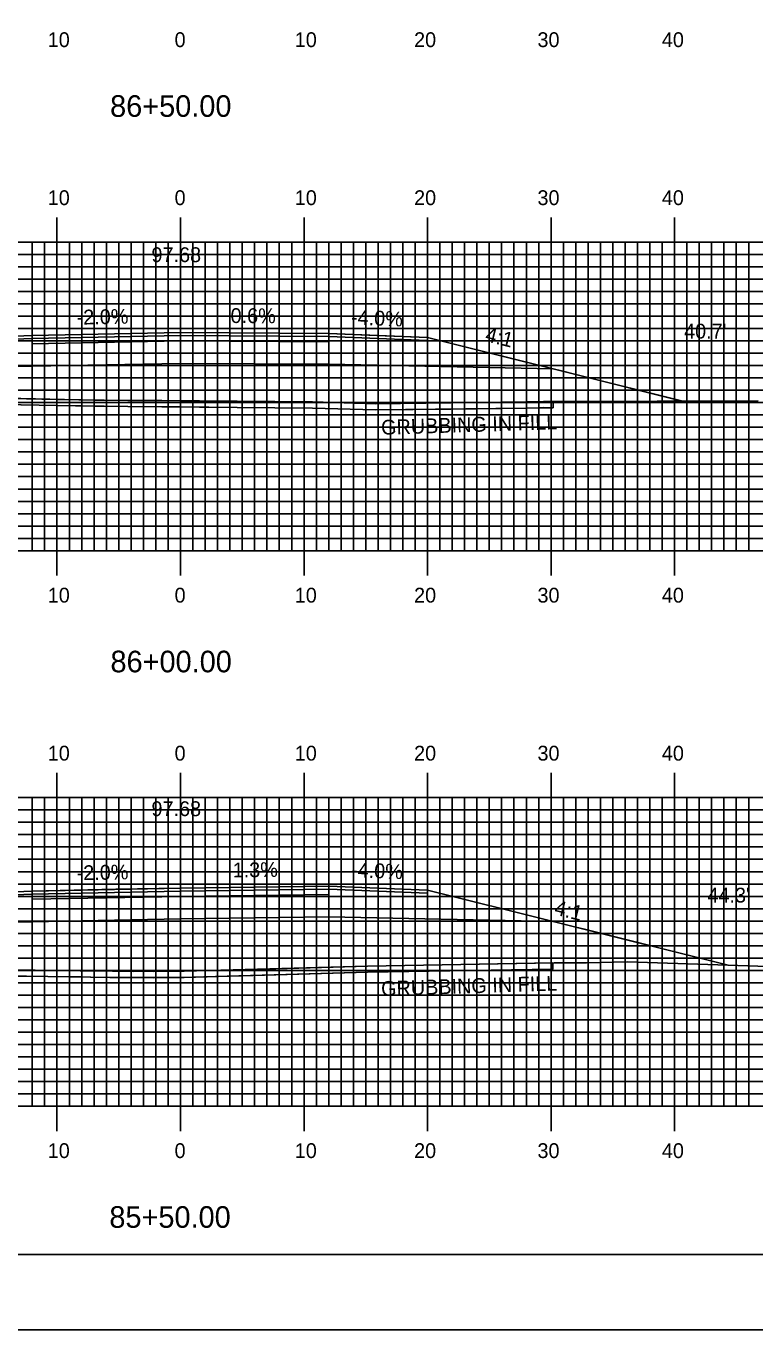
# Model space of a CAD drawing. Extents: x 1763759 to 1764102, y 442591 to 442811.
# Drawn here: x 1763911.8 to 1763970.8, y 442590.5 to 442696.2 of the extents above; entities that cross this region are included whole.
import ezdxf

# ---------------------------------------------------------------- set-up
doc = ezdxf.new("R2010")
doc.units = 0
for name, color, linetype in [('ANNOTATION', 7, 'Continuous'), ('BORDER', 7, 'Continuous'), ('D_Roadway_Centerline', 7, 'Continuous'), ('D_Roadway_Centerline_Text', 7, 'Continuous'), ('D_Roadway_Edge_Shoulder', 7, 'Continuous'), ('D_Roadway_Edge_TW', 7, 'Continuous'), ('D_Roadway_Pavement', 7, 'Continuous'), ('D_Roadway_SlopeLines', 7, 'Continuous'), ('D_Roadway_SubGrade', 7, 'Continuous'), ('D_Text_Standard', 7, 'Continuous'), ('GRUBBING IN FILL', 7, 'Continuous'), ('H_V ANNOTATION', 7, 'Continuous'), ('MAJOR', 7, 'Continuous'), ('MINOR', 7, 'Continuous'), ('PLOT BOUNDARY', 7, 'Continuous'), ('S_Roadway_Centerline', 7, 'Continuous')]:
    doc.layers.add(name, color=color, linetype=linetype)

msp = doc.modelspace()

# ---------------------------------------------------------------- linework, layer by layer
at = {"layer": 'BORDER'}
msp.add_lwpolyline([(1763774.72, 442596.67), (1764094.72, 442596.67), (1764094.72, 442806.67), (1763774.72, 442806.67)], close=True, dxfattribs=at)
at = {"layer": 'D_Roadway_Centerline'}
for points in [[(1763887.29, 442666.53), (1763894.14, 442668.24), (1763894.15, 442668.24), (1763901.63, 442670.11), (1763904.32, 442670.79), (1763906.87, 442670.89), (1763912.31, 442671.11), (1763912.32, 442671.11), (1763924.31, 442671.35), (1763924.32, 442671.35), (1763924.32, 442671.35), (1763936.32, 442671.27), (1763936.32, 442671.27), (1763940.22, 442671.11), (1763944.32, 442670.95), (1763944.33, 442670.95), (1763950.59, 442669.38), (1763954.49, 442668.4), (1763955.16, 442668.24), (1763956.32, 442667.95), (1763964.82, 442665.82), (1763964.98, 442665.78)], [(1763883.9, 442620.67), (1763894.14, 442623.23), (1763894.14, 442623.24), (1763904.32, 442625.78), (1763904.32, 442625.78), (1763912.31, 442626.1), (1763912.32, 442626.1), (1763919.08, 442626.24), (1763924.31, 442626.34), (1763924.32, 442626.34), (1763936.31, 442626.5), (1763936.32, 442626.5), (1763936.32, 442626.5), (1763944.32, 442626.18), (1763954.49, 442623.64), (1763954.49, 442623.63), (1763956.32, 442623.18), (1763957.04, 442623), (1763968.66, 442620.09)]]:
    msp.add_lwpolyline(points, dxfattribs=at)
at = {"layer": 'D_Roadway_Edge_Shoulder'}
for points in [[(1763912.32, 442671.11), (1763904.32, 442670.79), (1763904.32, 442670.54), (1763912.32, 442670.86)], [(1763936.32, 442671.27), (1763944.32, 442670.95), (1763944.32, 442670.7), (1763936.32, 442671.02)], [(1763912.32, 442626.1), (1763904.32, 442625.78), (1763904.32, 442625.53), (1763912.32, 442625.85)], [(1763936.32, 442626.5), (1763944.32, 442626.18), (1763944.32, 442625.93), (1763936.32, 442626.25)]]:
    msp.add_lwpolyline(points, close=True, dxfattribs=at)
at = {"layer": 'D_Roadway_Edge_TW'}
for points in [[(1763912.32, 442670.86), (1763912.32, 442671.11), (1763924.32, 442671.35), (1763936.32, 442671.27), (1763936.32, 442671.02), (1763924.32, 442671.1)], [(1763936.32, 442671.27), (1763936.32, 442671.27), (1763936.32, 442671.02), (1763936.32, 442671.02)], [(1763912.32, 442625.85), (1763912.32, 442626.1), (1763924.32, 442626.34), (1763936.32, 442626.5), (1763936.32, 442626.25), (1763924.32, 442626.09)], [(1763936.32, 442626.5), (1763936.32, 442626.5), (1763936.32, 442626.25), (1763936.32, 442626.25)]]:
    msp.add_lwpolyline(points, close=True, dxfattribs=at)
at = {"layer": 'D_Roadway_Pavement'}
for points in [[(1763912.32, 442670.44), (1763912.32, 442670.86), (1763924.32, 442671.1), (1763936.32, 442671.02), (1763936.32, 442670.6), (1763924.32, 442670.68)], [(1763936.32, 442671.02), (1763936.32, 442671.02), (1763936.32, 442670.6), (1763936.32, 442670.6)], [(1763912.32, 442625.43), (1763912.32, 442625.85), (1763924.32, 442626.09), (1763936.32, 442626.25), (1763936.32, 442625.83), (1763924.32, 442625.67)], [(1763936.32, 442626.25), (1763936.32, 442626.25), (1763936.32, 442625.83), (1763936.32, 442625.83)]]:
    msp.add_lwpolyline(points, close=True, dxfattribs=at)
for points in [[(1763936.32, 442671.02), (1763936.32, 442670.6)], [(1763936.32, 442671.02), (1763936.32, 442670.6)], [(1763936.32, 442671.02), (1763936.32, 442670.6)], [(1763936.32, 442626.25), (1763936.32, 442625.83)], [(1763936.32, 442626.25), (1763936.32, 442625.83)], [(1763936.32, 442626.25), (1763936.32, 442625.83)]]:
    msp.add_lwpolyline(points, dxfattribs=at)
at = {"layer": 'D_Roadway_SlopeLines'}
for points in [[(1763944.32, 442670.95), (1763954.49, 442668.4), (1763956.32, 442667.95), (1763964.98, 442665.78)], [(1763944.32, 442626.18), (1763954.49, 442623.63), (1763956.32, 442623.18), (1763968.66, 442620.09)]]:
    msp.add_lwpolyline(points, dxfattribs=at)
at = {"layer": 'D_Roadway_SubGrade'}
for points in [[(1763904.32, 442670.54), (1763912.32, 442670.86), (1763912.32, 442670.44), (1763912.32, 442668.61), (1763894.14, 442668.24), (1763904.32, 442670.79)], [(1763912.32, 442668.61), (1763912.32, 442670.44), (1763924.32, 442670.68), (1763936.32, 442670.6), (1763936.32, 442668.77), (1763924.32, 442668.85)], [(1763936.32, 442670.6), (1763936.32, 442671.02), (1763944.32, 442670.7), (1763944.32, 442670.95), (1763954.49, 442668.4), (1763936.32, 442668.77)], [(1763936.32, 442670.6), (1763936.32, 442670.6), (1763936.32, 442668.77), (1763936.32, 442668.77)], [(1763904.32, 442625.53), (1763912.32, 442625.85), (1763912.32, 442625.43), (1763912.32, 442623.6), (1763894.14, 442623.24), (1763904.32, 442625.78)], [(1763912.32, 442623.6), (1763912.32, 442625.43), (1763924.32, 442625.67), (1763936.32, 442625.83), (1763936.32, 442624), (1763924.32, 442623.84)], [(1763936.32, 442625.83), (1763936.32, 442626.25), (1763944.32, 442625.93), (1763944.32, 442626.18), (1763954.49, 442623.63), (1763936.32, 442624)], [(1763936.32, 442625.83), (1763936.32, 442625.83), (1763936.32, 442624), (1763936.32, 442624)]]:
    msp.add_lwpolyline(points, close=True, dxfattribs=at)
at = {"layer": 'GRUBBING IN FILL'}
for p, q in [((1763954.49, 442665.75), (1763954.49, 442665.25)), ((1763954.47, 442619.78), (1763954.47, 442620.28))]:
    msp.add_line(p, q, dxfattribs=at)
for points in [[(1763894.14, 442668.24), (1763912.32, 442668.61), (1763924.32, 442668.85), (1763936.32, 442668.77), (1763954.49, 442668.4)], [(1763894.14, 442665.85), (1763899.76, 442665.71), (1763911.39, 442665.49), (1763917.28, 442665.37), (1763922.81, 442665.34), (1763935.01, 442665.23), (1763940.12, 442665.08), (1763952.29, 442665.22), (1763953.27, 442665.24), (1763953.7, 442665.26), (1763954.47, 442665.25)], [(1763894.22, 442619.74), (1763903.78, 442619.27), (1763908.34, 442619.25), (1763918.82, 442619.1), (1763922.15, 442619.08), (1763924.62, 442619.11), (1763939.47, 442619.52), (1763954.47, 442619.78)]]:
    msp.add_lwpolyline(points, dxfattribs=at)
for points in [[(1763894.14, 442666.35), (1763894.14, 442665.85), (1763896.95, 442665.78), (1763905.58, 442665.6), (1763914.34, 442665.43), (1763920.05, 442665.35), (1763924.32, 442665.32), (1763924.32, 442665.82), (1763920.05, 442665.85), (1763914.34, 442665.93), (1763905.58, 442666.1), (1763899.76, 442666.21)], [(1763894.14, 442666.35), (1763894.14, 442665.85), (1763896.95, 442665.78), (1763905.58, 442665.6), (1763914.34, 442665.43), (1763920.05, 442665.35), (1763924.32, 442665.32), (1763924.32, 442665.82), (1763920.05, 442665.85), (1763914.34, 442665.93), (1763905.58, 442666.1), (1763899.76, 442666.21)], [(1763924.32, 442665.82), (1763928.91, 442665.78), (1763935.01, 442665.73), (1763937.57, 442665.66), (1763940.12, 442665.58), (1763946.2, 442665.65), (1763954.49, 442665.75), (1763954.49, 442665.25), (1763952.29, 442665.22), (1763946.2, 442665.15), (1763940.12, 442665.08), (1763935.01, 442665.23), (1763928.91, 442665.28), (1763924.32, 442665.32)], [(1763924.32, 442665.82), (1763928.91, 442665.78), (1763935.01, 442665.73), (1763937.57, 442665.66), (1763940.12, 442665.58), (1763946.2, 442665.65), (1763954.49, 442665.75), (1763954.49, 442665.25), (1763952.29, 442665.22), (1763946.2, 442665.15), (1763940.12, 442665.08), (1763935.01, 442665.23), (1763928.91, 442665.28), (1763924.32, 442665.32)], [(1763894.22, 442619.74), (1763903.78, 442619.27), (1763913.58, 442619.17), (1763916.38, 442619.14), (1763917.03, 442619.13), (1763918.6, 442619.1), (1763920.48, 442619.09), (1763924.32, 442619.1), (1763924.32, 442619.6), (1763920.48, 442619.59), (1763918.82, 442619.6), (1763913.58, 442619.67), (1763908.34, 442619.75), (1763903.78, 442619.77), (1763897.63, 442620.07), (1763894.22, 442620.24)], [(1763894.22, 442619.74), (1763903.78, 442619.27), (1763913.58, 442619.17), (1763916.38, 442619.14), (1763917.03, 442619.13), (1763918.6, 442619.1), (1763920.48, 442619.09), (1763924.32, 442619.1), (1763924.32, 442619.6), (1763920.48, 442619.59), (1763918.82, 442619.6), (1763913.58, 442619.67), (1763908.34, 442619.75), (1763903.78, 442619.77), (1763897.63, 442620.07), (1763894.22, 442620.24)], [(1763924.32, 442619.6), (1763932.04, 442619.81), (1763939.47, 442620.02), (1763947.01, 442620.15), (1763954.47, 442620.28), (1763954.47, 442619.78), (1763939.47, 442619.52), (1763924.32, 442619.1)], [(1763924.32, 442619.6), (1763932.04, 442619.81), (1763939.47, 442620.02), (1763947.01, 442620.15), (1763954.47, 442620.28), (1763954.47, 442619.78), (1763939.47, 442619.52), (1763924.32, 442619.1)]]:
    msp.add_lwpolyline(points, close=True, dxfattribs=at)
at = {"layer": 'MAJOR'}
for p, q in [((1763914.32, 442680.67), (1763914.32, 442678.67)), ((1763924.32, 442680.67), (1763924.32, 442678.67)), ((1763934.32, 442680.67), (1763934.32, 442678.67)), ((1763944.32, 442680.67), (1763944.32, 442678.67)), ((1763954.32, 442680.67), (1763954.32, 442678.67)), ((1763964.32, 442680.67), (1763964.32, 442678.67)), ((1763784.32, 442678.67), (1764064.32, 442678.67)), ((1763784.32, 442678.67), (1764064.32, 442678.67)), ((1763914.32, 442653.67), (1763914.32, 442678.67)), ((1763924.32, 442653.67), (1763924.32, 442678.67)), ((1763934.32, 442653.67), (1763934.32, 442678.67)), ((1763944.32, 442653.67), (1763944.32, 442678.67)), ((1763954.32, 442653.67), (1763954.32, 442678.67)), ((1763964.32, 442653.67), (1763964.32, 442678.67)), ((1763784.32, 442673.67), (1764064.32, 442673.67)), ((1763784.32, 442668.67), (1764064.32, 442668.67)), ((1763784.32, 442663.67), (1764064.32, 442663.67)), ((1763784.32, 442658.67), (1764064.32, 442658.67)), ((1763784.32, 442653.67), (1764064.32, 442653.67)), ((1763784.32, 442653.67), (1764064.32, 442653.67)), ((1763914.32, 442651.66), (1763914.32, 442653.67)), ((1763924.32, 442651.66), (1763924.32, 442653.67)), ((1763934.32, 442651.66), (1763934.32, 442653.67)), ((1763944.32, 442651.66), (1763944.32, 442653.67)), ((1763954.32, 442651.66), (1763954.32, 442653.67)), ((1763964.32, 442651.66), (1763964.32, 442653.67)), ((1763914.32, 442635.67), (1763914.32, 442633.67)), ((1763924.32, 442635.67), (1763924.32, 442633.67)), ((1763934.32, 442635.67), (1763934.32, 442633.67)), ((1763944.32, 442635.67), (1763944.32, 442633.67)), ((1763954.32, 442635.67), (1763954.32, 442633.67)), ((1763964.32, 442635.67), (1763964.32, 442633.67)), ((1763784.32, 442633.67), (1764064.32, 442633.67)), ((1763784.32, 442633.67), (1764064.32, 442633.67)), ((1763914.32, 442608.67), (1763914.32, 442633.67)), ((1763924.32, 442608.67), (1763924.32, 442633.67)), ((1763934.32, 442608.67), (1763934.32, 442633.67)), ((1763944.32, 442608.67), (1763944.32, 442633.67)), ((1763954.32, 442608.67), (1763954.32, 442633.67)), ((1763964.32, 442608.67), (1763964.32, 442633.67)), ((1763784.32, 442628.67), (1764064.32, 442628.67)), ((1763784.32, 442623.67), (1764064.32, 442623.67)), ((1763784.32, 442618.67), (1764064.32, 442618.67)), ((1763784.32, 442613.67), (1764064.32, 442613.67)), ((1763784.32, 442608.67), (1764064.32, 442608.67)), ((1763784.32, 442608.67), (1764064.32, 442608.67)), ((1763914.32, 442606.66), (1763914.32, 442608.67)), ((1763924.32, 442606.66), (1763924.32, 442608.67)), ((1763934.32, 442606.66), (1763934.32, 442608.67)), ((1763944.32, 442606.66), (1763944.32, 442608.67)), ((1763954.32, 442606.66), (1763954.32, 442608.67)), ((1763964.32, 442606.66), (1763964.32, 442608.67))]:
    msp.add_line(p, q, dxfattribs=at)
at = {"layer": 'MINOR'}
for p, q in [((1763912.32, 442653.67), (1763912.32, 442678.67)), ((1763913.32, 442653.67), (1763913.32, 442678.67)), ((1763915.32, 442653.67), (1763915.32, 442678.67)), ((1763916.32, 442653.67), (1763916.32, 442678.67)), ((1763917.32, 442653.67), (1763917.32, 442678.67)), ((1763918.32, 442653.67), (1763918.32, 442678.67)), ((1763919.32, 442653.67), (1763919.32, 442678.67)), ((1763920.32, 442653.67), (1763920.32, 442678.67)), ((1763921.32, 442653.67), (1763921.32, 442678.67)), ((1763922.32, 442653.67), (1763922.32, 442678.67)), ((1763923.32, 442653.67), (1763923.32, 442678.67)), ((1763925.32, 442653.67), (1763925.32, 442678.67)), ((1763926.32, 442653.67), (1763926.32, 442678.67)), ((1763927.32, 442653.67), (1763927.32, 442678.67)), ((1763928.32, 442653.67), (1763928.32, 442678.67)), ((1763929.32, 442653.67), (1763929.32, 442678.67)), ((1763930.32, 442653.67), (1763930.32, 442678.67)), ((1763931.32, 442653.67), (1763931.32, 442678.67)), ((1763932.32, 442653.67), (1763932.32, 442678.67)), ((1763933.32, 442653.67), (1763933.32, 442678.67)), ((1763935.32, 442653.67), (1763935.32, 442678.67)), ((1763936.32, 442653.67), (1763936.32, 442678.67)), ((1763937.32, 442653.67), (1763937.32, 442678.67)), ((1763938.32, 442653.67), (1763938.32, 442678.67)), ((1763939.32, 442653.67), (1763939.32, 442678.67)), ((1763940.32, 442653.67), (1763940.32, 442678.67)), ((1763941.32, 442653.67), (1763941.32, 442678.67)), ((1763942.32, 442653.67), (1763942.32, 442678.67)), ((1763943.32, 442653.67), (1763943.32, 442678.67)), ((1763945.32, 442653.67), (1763945.32, 442678.67)), ((1763946.32, 442653.67), (1763946.32, 442678.67)), ((1763947.32, 442653.67), (1763947.32, 442678.67)), ((1763948.32, 442653.67), (1763948.32, 442678.67)), ((1763949.32, 442653.67), (1763949.32, 442678.67)), ((1763950.32, 442653.67), (1763950.32, 442678.67)), ((1763951.32, 442653.67), (1763951.32, 442678.67)), ((1763952.32, 442653.67), (1763952.32, 442678.67)), ((1763953.32, 442653.67), (1763953.32, 442678.67)), ((1763955.32, 442653.67), (1763955.32, 442678.67)), ((1763956.32, 442653.67), (1763956.32, 442678.67)), ((1763957.32, 442653.67), (1763957.32, 442678.67)), ((1763958.32, 442653.67), (1763958.32, 442678.67)), ((1763959.32, 442653.67), (1763959.32, 442678.67)), ((1763960.32, 442653.67), (1763960.32, 442678.67)), ((1763961.32, 442653.67), (1763961.32, 442678.67)), ((1763962.32, 442653.67), (1763962.32, 442678.67)), ((1763963.32, 442653.67), (1763963.32, 442678.67)), ((1763965.32, 442653.67), (1763965.32, 442678.67)), ((1763966.32, 442653.67), (1763966.32, 442678.67)), ((1763967.32, 442653.67), (1763967.32, 442678.67)), ((1763968.32, 442653.67), (1763968.32, 442678.67)), ((1763969.32, 442653.67), (1763969.32, 442678.67)), ((1763970.32, 442653.67), (1763970.32, 442678.67)), ((1763784.32, 442677.67), (1764064.32, 442677.67)), ((1763784.32, 442676.67), (1764064.32, 442676.67)), ((1763784.32, 442675.67), (1764064.32, 442675.67)), ((1763784.32, 442674.67), (1764064.32, 442674.67)), ((1763784.32, 442672.67), (1764064.32, 442672.67)), ((1763784.32, 442671.67), (1764064.32, 442671.67)), ((1763784.32, 442670.67), (1764064.32, 442670.67)), ((1763784.32, 442669.67), (1764064.32, 442669.67)), ((1763784.32, 442667.67), (1764064.32, 442667.67)), ((1763784.32, 442666.67), (1764064.32, 442666.67)), ((1763784.32, 442665.67), (1764064.32, 442665.67)), ((1763784.32, 442664.67), (1764064.32, 442664.67)), ((1763784.32, 442662.67), (1764064.32, 442662.67)), ((1763784.32, 442661.67), (1764064.32, 442661.67)), ((1763784.32, 442660.67), (1764064.32, 442660.67)), ((1763784.32, 442659.67), (1764064.32, 442659.67)), ((1763784.32, 442657.67), (1764064.32, 442657.67)), ((1763784.32, 442656.67), (1764064.32, 442656.67)), ((1763784.32, 442655.67), (1764064.32, 442655.67)), ((1763784.32, 442654.67), (1764064.32, 442654.67)), ((1763912.32, 442608.67), (1763912.32, 442633.67)), ((1763913.32, 442608.67), (1763913.32, 442633.67)), ((1763915.32, 442608.67), (1763915.32, 442633.67)), ((1763916.32, 442608.67), (1763916.32, 442633.67)), ((1763917.32, 442608.67), (1763917.32, 442633.67)), ((1763918.32, 442608.67), (1763918.32, 442633.67)), ((1763919.32, 442608.67), (1763919.32, 442633.67)), ((1763920.32, 442608.67), (1763920.32, 442633.67)), ((1763921.32, 442608.67), (1763921.32, 442633.67)), ((1763922.32, 442608.67), (1763922.32, 442633.67)), ((1763923.32, 442608.67), (1763923.32, 442633.67)), ((1763925.32, 442608.67), (1763925.32, 442633.67)), ((1763926.32, 442608.67), (1763926.32, 442633.67)), ((1763927.32, 442608.67), (1763927.32, 442633.67)), ((1763928.32, 442608.67), (1763928.32, 442633.67)), ((1763929.32, 442608.67), (1763929.32, 442633.67)), ((1763930.32, 442608.67), (1763930.32, 442633.67)), ((1763931.32, 442608.67), (1763931.32, 442633.67)), ((1763932.32, 442608.67), (1763932.32, 442633.67)), ((1763933.32, 442608.67), (1763933.32, 442633.67)), ((1763935.32, 442608.67), (1763935.32, 442633.67)), ((1763936.32, 442608.67), (1763936.32, 442633.67)), ((1763937.32, 442608.67), (1763937.32, 442633.67)), ((1763938.32, 442608.67), (1763938.32, 442633.67)), ((1763939.32, 442608.67), (1763939.32, 442633.67)), ((1763940.32, 442608.67), (1763940.32, 442633.67)), ((1763941.32, 442608.67), (1763941.32, 442633.67)), ((1763942.32, 442608.67), (1763942.32, 442633.67)), ((1763943.32, 442608.67), (1763943.32, 442633.67)), ((1763945.32, 442608.67), (1763945.32, 442633.67)), ((1763946.32, 442608.67), (1763946.32, 442633.67)), ((1763947.32, 442608.67), (1763947.32, 442633.67)), ((1763948.32, 442608.67), (1763948.32, 442633.67)), ((1763949.32, 442608.67), (1763949.32, 442633.67)), ((1763950.32, 442608.67), (1763950.32, 442633.67)), ((1763951.32, 442608.67), (1763951.32, 442633.67)), ((1763952.32, 442608.67), (1763952.32, 442633.67)), ((1763953.32, 442608.67), (1763953.32, 442633.67)), ((1763955.32, 442608.67), (1763955.32, 442633.67)), ((1763956.32, 442608.67), (1763956.32, 442633.67)), ((1763957.32, 442608.67), (1763957.32, 442633.67)), ((1763958.32, 442608.67), (1763958.32, 442633.67)), ((1763959.32, 442608.67), (1763959.32, 442633.67)), ((1763960.32, 442608.67), (1763960.32, 442633.67)), ((1763961.32, 442608.67), (1763961.32, 442633.67)), ((1763962.32, 442608.67), (1763962.32, 442633.67)), ((1763963.32, 442608.67), (1763963.32, 442633.67)), ((1763965.32, 442608.67), (1763965.32, 442633.67)), ((1763966.32, 442608.67), (1763966.32, 442633.67)), ((1763967.32, 442608.67), (1763967.32, 442633.67)), ((1763968.32, 442608.67), (1763968.32, 442633.67)), ((1763969.32, 442608.67), (1763969.32, 442633.67)), ((1763970.32, 442608.67), (1763970.32, 442633.67)), ((1763784.32, 442632.67), (1764064.32, 442632.67)), ((1763784.32, 442631.67), (1764064.32, 442631.67)), ((1763784.32, 442630.67), (1764064.32, 442630.67)), ((1763784.32, 442629.67), (1764064.32, 442629.67)), ((1763784.32, 442627.67), (1764064.32, 442627.67)), ((1763784.32, 442626.67), (1764064.32, 442626.67)), ((1763784.32, 442625.67), (1764064.32, 442625.67)), ((1763784.32, 442624.67), (1764064.32, 442624.67)), ((1763784.32, 442622.67), (1764064.32, 442622.67)), ((1763784.32, 442621.67), (1764064.32, 442621.67)), ((1763784.32, 442620.67), (1764064.32, 442620.67)), ((1763784.32, 442619.67), (1764064.32, 442619.67)), ((1763784.32, 442617.67), (1764064.32, 442617.67)), ((1763784.32, 442616.67), (1764064.32, 442616.67)), ((1763784.32, 442615.67), (1764064.32, 442615.67)), ((1763784.32, 442614.67), (1764064.32, 442614.67)), ((1763784.32, 442612.67), (1764064.32, 442612.67)), ((1763784.32, 442611.67), (1764064.32, 442611.67)), ((1763784.32, 442610.67), (1764064.32, 442610.67)), ((1763784.32, 442609.67), (1764064.32, 442609.67))]:
    msp.add_line(p, q, dxfattribs=at)
at = {"layer": 'PLOT BOUNDARY'}
msp.add_lwpolyline([(1763758.53, 442590.55), (1764098.53, 442590.55), (1764098.53, 442810.55), (1763758.53, 442810.55)], close=True, dxfattribs=at)
at = {"layer": 'S_Roadway_Centerline'}
for points in [[(1763863.88, 442666.68), (1763865.48, 442666.68), (1763869.39, 442666.69), (1763882.25, 442666.67), (1763890.84, 442666.43), (1763899.76, 442666.21), (1763911.39, 442665.99), (1763917.28, 442665.87), (1763922.81, 442665.84), (1763935.01, 442665.73), (1763940.12, 442665.58), (1763952.29, 442665.72), (1763953.27, 442665.74), (1763953.7, 442665.76), (1763954.72, 442665.75), (1763971.09, 442665.8)], [(1763860.52, 442620.85), (1763867.82, 442620.86), (1763870.65, 442620.92), (1763877.79, 442620.81), (1763885.59, 442620.64), (1763891.48, 442620.37), (1763903.78, 442619.77), (1763908.34, 442619.75), (1763918.82, 442619.6), (1763922.15, 442619.58), (1763924.62, 442619.61), (1763939.47, 442620.02), (1763954.56, 442620.28), (1763957.18, 442620.29), (1763960.52, 442620.37), (1763975.15, 442619.87)]]:
    msp.add_lwpolyline(points, dxfattribs=at)

# ---------------------------------------------------------------- texts
at = {"layer": 'ANNOTATION'}
for s, rotation, p in [('-2.0%', 1.1457, (1763915.92, 442671.98)), ('0.6%', 359.6324, (1763928.37, 442672.12)), ('-4.0%', 357.7092, (1763938.11, 442672)), ('4:1', 345.9618, (1763948.92, 442670.66)), ('-2.0%', 1.1458, (1763915.92, 442626.97)), ('1.3%', 0.7543, (1763928.55, 442627.2)), ('-4.0%', 357.7095, (1763938.11, 442627.23)), ('4:1', 345.9606, (1763954.52, 442624.22))]:
    msp.add_text(s, height=1.2, rotation=rotation, dxfattribs=at).set_placement(p)
at = {"layer": 'D_Roadway_Centerline'}
for s, p in [('C', (1763924.31, 442671.35)), ('L', (1763924.32, 442671.34)), ('C', (1763924.31, 442626.34)), ('L', (1763924.32, 442626.33))]:
    msp.add_text(s, height=0.0146, dxfattribs=at).set_placement(p)
at = {"layer": 'D_Roadway_Centerline_Text'}
for p in [(1763921.97, 442677.05), (1763921.97, 442632.17)]:
    msp.add_text('97.68', height=1.2, dxfattribs=at).set_placement(p)
at = {"layer": 'D_Text_Standard'}
for s, p in [("40.7'", (1763965.09, 442670.86)), ("44.3'", (1763966.98, 442625.17))]:
    msp.add_text(s, height=1.2, dxfattribs=at).set_placement(p)
at = {"layer": 'GRUBBING IN FILL'}
for p in [(1763940.58, 442663.06), (1763940.58, 442617.59)]:
    msp.add_text('GRUBBING IN FILL', height=1.2, rotation=1.8202, dxfattribs=at).set_placement(p)
at = {"layer": 'H_V ANNOTATION'}
for s, height, p in [('10', 1.2, (1763913.57, 442694.47)), ('0', 1.2, (1763923.84, 442694.47)), ('10', 1.2, (1763933.57, 442694.47)), ('20', 1.2, (1763943.23, 442694.47)), ('30', 1.2, (1763953.22, 442694.47)), ('40', 1.2, (1763963.29, 442694.47)), ('86+50.00', 1.75, (1763918.62, 442688.82)), ('10', 1.2, (1763913.57, 442681.67)), ('0', 1.2, (1763923.84, 442681.67)), ('10', 1.2, (1763933.57, 442681.67)), ('20', 1.2, (1763943.23, 442681.67)), ('30', 1.2, (1763953.22, 442681.67)), ('40', 1.2, (1763963.29, 442681.67)), ('10', 1.2, (1763913.57, 442649.47)), ('0', 1.2, (1763923.84, 442649.47)), ('10', 1.2, (1763933.57, 442649.47)), ('20', 1.2, (1763943.23, 442649.47)), ('30', 1.2, (1763953.22, 442649.47)), ('40', 1.2, (1763963.29, 442649.47)), ('86+00.00', 1.75, (1763918.65, 442643.82)), ('10', 1.2, (1763913.57, 442636.67)), ('0', 1.2, (1763923.84, 442636.67)), ('10', 1.2, (1763933.57, 442636.67)), ('20', 1.2, (1763943.23, 442636.67)), ('30', 1.2, (1763953.22, 442636.67)), ('40', 1.2, (1763963.29, 442636.67)), ('10', 1.2, (1763913.57, 442604.47)), ('0', 1.2, (1763923.84, 442604.47)), ('10', 1.2, (1763933.57, 442604.47)), ('20', 1.2, (1763943.23, 442604.47)), ('30', 1.2, (1763953.22, 442604.47)), ('40', 1.2, (1763963.29, 442604.47)), ('85+50.00', 1.75, (1763918.56, 442598.82))]:
    msp.add_text(s, height=height, dxfattribs=at).set_placement(p)

doc.saveas('drawing.dxf')
